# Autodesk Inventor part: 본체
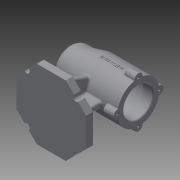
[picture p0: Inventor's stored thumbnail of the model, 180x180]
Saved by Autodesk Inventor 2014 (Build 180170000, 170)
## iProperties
Created: 2021-01
Part Number: 본체
Material: Generic
Document SubType Name: Modeling
Designer: kh
Density: 1 g/cm^3
Appearance: Default
Mass: 233.583 g
Surface Area: 614.637 cm^2
Volume: 233.583 cm^3
Author: kh
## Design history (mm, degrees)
sketch "Sketch1"
  geometry: L1 (-20.711, 50)-(20.711, 50); L2 (20.711, 50)-(50, 20.711); L3 (50, 20.711)-(50, -20.711); L4 (50, -20.711)-(20.711, -50); L5 (20.711, -50)-(-20.711, -50); L6 (-20.711, -50)-(-50, -20.711); L7 (-50, -20.711)-(-50, 20.711); L8 (-50, 20.711)-(-20.711, 50); 2 further points
  constraints: 16 end point, 1 coincident, 1 horizontal, 17 other
  dimensions: "d0" = 50 distance from line of L3 point (0, 0)
extrude "Extrusion1" new body sketch "Sketch1" distance "d1" = 10; taper "d2" = 0 deg
sketch "Sketch3"
  geometry: L1 (0, 0)-(0, 32.527); L2 (-50, 75)-(50, 75); L3 (-50, 75)-(-50, 100); L4 (-50, 100)-(-30, 100); L5 (-30, 100)-(-10, 105); L6 (-10, 105)-(50, 105); L7 (50, 105)-(50, 75); L8 (-20.711, 0)-(20.711, 0) reference; L9 (50, 0)-(50, 10) reference; L10 (-44, 75)-(-44, 85.5); L11 (-44, 85.5)-(-41, 85.5); L12 (-41, 85.5)-(-41, 91); L13 (-41, 91)-(-37, 91); L14 (-37, 91)-(-37, 92.5); L15 (-37, 92.5)-(-19, 92.5); L16 (35, 99)-(35, 96); L17 (35, 96)-(50, 96); L18 (-19, 92.5)-(-19, 96); L19 (-19, 96)-(-7, 96); L20 (-7, 96)-(-7, 99); L21 (-7, 99)-(35, 99)
  constraints: 38 end point, 8 perpendicular, 7 parallel, 2 point on line, 1 collinear, 1 horizontal, 1 vertical
  dimensions: "d3" = 60 diameter of L6 L2; "d4" = 20 distance from line of L4.end L3; "d5" = 40 distance from line of L5.end L3; "d6" = 100 distance between parallel lines of L7 L3; "d7" = 75 distance between parallel lines of L8 L2; "d8" = 50 diameter of L4 L2; "d9" = 21 diameter of L11 L2; "d10" = 32 diameter of L13 L2; "d11" = 35 diameter of L15 L2; "d12" = 42 diameter of L19 L2; "d13" = 48 diameter of L21 L2; "d14" = 42 diameter of L17 L2; "d15" = 15 distance between parallel lines of L16 L7; "d16" = 42 distance between parallel lines of L20 L16; "d17" = 12 distance between parallel lines of L18 L20; "d18" = 18 distance between parallel lines of L14 L18; "d19" = 4 distance between parallel lines of L12 L14; "d20" = 3 distance between parallel lines of L10 L12
revolve "Revolution1" sketch "Sketch3" stored, may be unused: angle "d21" = 90 deg
sketch "Sketch5"
  geometry: L1 (20.711, 10)-(-20.711, 10) reference; L2 (-20.711, 10)-(-50, 10) reference; L3 (50, 10)-(20.711, 10) reference; L4 (-27, 10)-(-21.119, 40.257); L5 (-50, 0)-(-50, 10) reference; L6 (27, 10)-(27, 36.527); L7 (50, 0)-(50, 10) reference; 1 further point
  constraints: 4 end point, 2 point on line, 1 parallel
  dimensions: "d22" = 23 distance from line of L5 L4.start; "d23" = 101 deg angle of L4 L2; "d30" = 23 distance from line of L7 L6.start
feature "Rib1" dims "d24" = 1, "d25" = 8, "d26" = 0, "d27" = 0, "d28" = 1, "d29" = 1
feature "Rib2" dims "d31" = 1, "d32" = 8, "d33" = 0, "d34" = 0, "d35" = 1, "d36" = 1
sketch "Sketch6"
  geometry: L1 (10, 20.711)-(10, 50) reference; L2 (10, 35)-(32.836, 26.688); L3 (0, 50)-(10, 50) reference; L4 (10, -50)-(10, -20.711) reference; L5 (10, -35)-(35.757, -25.625); L6 (0, -50)-(10, -50) reference; 1 further point
  constraints: 4 end point, 2 point on line
  dimensions: "d37" = 15 distance from line of L3 L2.start; "d38" = 110 deg angle of L1 L2; "d45" = 15 distance from line of L6 L5.start; "d46" = 110 deg angle of L4 L5
feature "Rib3" dims "d39" = 1, "d40" = 8, "d41" = 0, "d42" = 0, "d43" = 1, "d44" = 1
feature "Rib4" dims "d47" = 1, "d48" = 8, "d49" = 0, "d50" = 0, "d51" = 1, "d52" = 1
sketch "Sketch7"
  geometry: L1 (-35.355, 35.355)-(35.355, -35.355); L2 (-35.355, -35.355)-(35.355, 35.355); L3 (-50, 0)-(50, 0); A1 r 50 centre (0, 0) between (-35.355, 35.355) and (35.355, -35.355); 6 further points
  constraints: 6 end point, 6 point on circle, 5 coincident, 3 midpoint, 1 centre point, 1 horizontal
  dimensions: "d53" = 100 diameter of A1; "d55" = 45 deg angle of L3 L1; "d56" = 45 deg angle of L2 L3
hole "Hole1" sketch "Sketch7" at (-35.355, 35.355), (35.355, 35.355), (35.355, -35.355), (-35.355, -35.355) diameter "d57" = 9; stored, may be unused: countersink angle "d61" = 90 deg, drill point angle "d63" = 0 deg; dims "d58" = 6, "d59" = 4, "d60" = 2, "d62" = 8
sketch "Sketch8"
  geometry: L1 (0, -30)-(0, 30); A1 r 30 centre (0, 0) between (0, -30) and (0, 30) reference; A2 r 6 centre (0, 30) between (5.97, 29.4) and (-5.97, 29.4); A3 r 30 centre (0, 0) between (5.97, 29.4) and (-5.97, 29.4); 1 further point
  constraints: 9 point on circle, 2 centre point, 2 end point, 1 coincident, 1 midpoint, 1 vertical
  dimensions: "d66" = 12 diameter of A2
extrude "Extrusion2" join sketch "Sketch8" distance "d67" = 16; taper "d68" = 0 deg
sketch "Sketch9"
  geometry: A1 r 6 centre (0, 0) between (5.97, -0.6) and (-5.97, -0.6) reference; 2 further points
  constraints: 1 coincident
hole "Hole2" sketch "Sketch9" at (0, 0) diameter "d69" = 3.459; stored, may be unused: countersink angle "d73" = 90 deg, drill point angle "d75" = 118 deg; dims "d70" = 8, "d71" = 4, "d72" = 2, "d74" = 10
pattern_circular "Circular Pattern1" dims angle "d77" = 360 deg
fillet "Fillet1" dims "d79" = 10
fillet "Fillet2" dims "d80" = 3
fillet "Fillet3" dims "d81" = 3
fillet "Fillet4" dims "d82" = 1
fillet "Fillet5" dims "d83" = 3
fillet "Fillet6" dims "d84" = 0.3
fillet "Fillet7" dims "d85" = 3
chamfer "Chamfer1" distance "d86" = 1; stored, may be unused: second distance "d87" = 2, angle "d88" = 45 deg
fillet "Fillet8" dims "d89" = 3
fillet "Fillet9" dims "d90" = 3
fillet "Fillet10" dims "d91" = 3
sketch "Sketch11"
  geometry: L1 (12.213, 82.916)-(53.209, 82.916); L2 (53.209, 82.916)-(53.209, 67.084); L3 (53.209, 67.084)-(12.213, 67.084); L4 (12.213, 67.084)-(12.213, 82.916); L5 (12.213, 75)-(53.209, 75); L6 (70.711, 81.771)-(70.711, 104.226) reference; L7 (-29.289, 60)-(-29.289, 90) reference; 3 further points
  constraints: 4 midpoint, 2 end point, 1 point on line, 2 other
  dimensions: "d92" = 38 distance from line of L6 point (32.711, 75)
emboss "Emboss1" sketch "Sketch11" dims "d93" = 0.5, "d94" = 0
body "Solid1"
